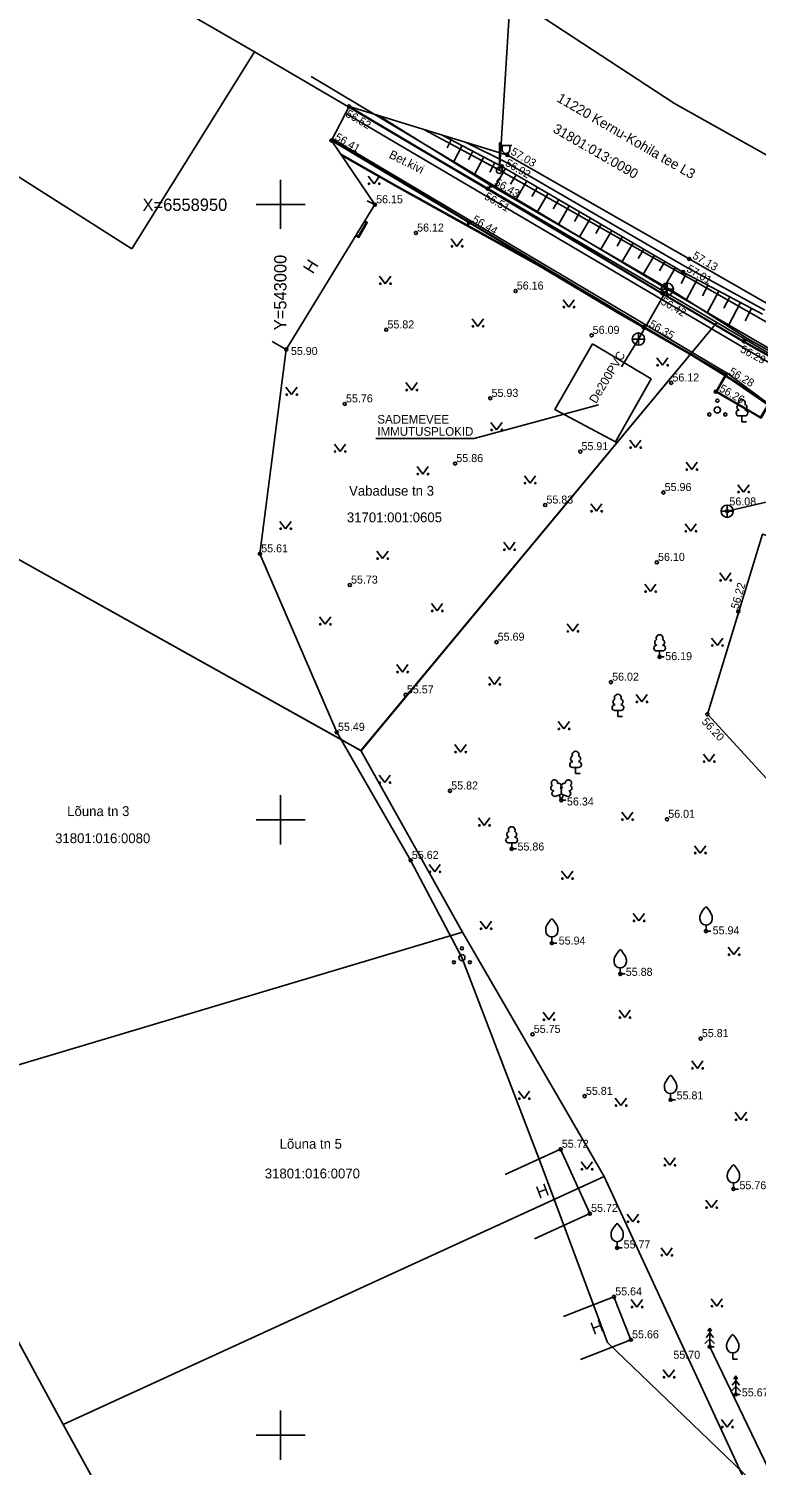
# Model space of a CAD drawing. Extents: x 542320 to 543602, y 6558748 to 6559969.
# Drawn here: x 542979.5 to 543038.7, y 6558847.6 to 6558964.3 of the extents above; entities that cross this region are included whole.
import ezdxf

# ---------------------------------------------------------------- set-up
doc = ezdxf.new("R2010")
doc.units = 0
for name, color, linetype in [('ABIJOONIS', 7, 'Continuous'), ('HALJASTUS', 7, 'Continuous'), ('HOONE', 7, 'Continuous'), ('HOONEDET', 7, 'Continuous'), ('KORGUS-EH2000', 7, 'Continuous'), ('mootpiir', 7, 'Continuous'), ('MPOHULIIN', 7, 'Continuous'), ('PIIR', 7, 'Continuous'), ('POST', 7, 'Continuous'), ('PUU', 7, 'Continuous'), ('RELJEEF', 7, 'Continuous'), ('SITRASS', 7, 'Continuous'), ('SKKAEV', 7, 'Continuous'), ('SKTRASS', 7, 'Continuous'), ('TEE', 7, 'Continuous'), ('VORK', 7, 'Continuous')]:
    doc.layers.add(name, color=color, linetype=linetype)

# ---------------------------------------------------------------- blocks, each defined once
blk = doc.blocks.new('VKORIS')
for p, q in [((0, 4), (0, -4)), ((-4, 0), (4, 0))]:
    blk.add_line(p, q)
blk = doc.blocks.new('VILJA1')
for p, q in [((0, 0), (0, 1)), ((0.8, 0), (0, 0))]:
    blk.add_line(p, q)
for points in [[(-1, 2), (-1, 2.3), (-0.98, 2.43), (-0.91, 2.69), (-0.79, 2.93), (-0.5, 3.4), (-0.18, 3.81), (0, 4)], [(1, 2), (1, 2.3), (0.98, 2.43), (0.91, 2.69), (0.79, 2.93), (0.5, 3.4), (0.18, 3.81), (0, 4)]]:
    blk.add_lwpolyline(points)
blk.add_arc((0, 2), 1, 180, 0)
blk = doc.blocks.new('KUUSK1')
for p, q in [((0, 3), (-0.3, 2.5)), ((0.3, 2.5), (0, 3)), ((0, 3), (0, 0)), ((0, 1.3), (-0.8, 0.5)), ((0, 2.2), (-0.6, 1.5)), ((0.6, 1.5), (0, 2.2)), ((0.8, 0.5), (0, 1.3)), ((0.72, 0), (0, 0))]:
    blk.add_line(p, q)
blk = doc.blocks.new('LEHTP1')
for p, q in [((0.48, 0.95), (-0.48, 0.95)), ((0, 0), (0, 0.95)), ((0.76, 0), (0, 0))]:
    blk.add_line(p, q)
for centre, radius, start, end in [((-0.34, 2.35), 0.465, 109.0217, 253.1415), ((0, 3.04), 0.554, 332.5799, 207.4201), ((0.34, 2.35), 0.465, 286.8508, 70.9859), ((-0.47, 1.42), 0.475, 90.0016, 269.3953), ((0.47, 1.42), 0.475, 270.6047, 89.9984)]:
    blk.add_arc(centre, radius, start, end)
blk = doc.blocks.new('MURU')
for p, q in [((-0.93, 1.21), (0, 0)), ((0, 0), (0.89, 1.21))]:
    blk.add_line(p, q)
for centre in [(-0.8, 0), (0.86, 0)]:
    blk.add_circle(centre, 0.11)
blk = doc.blocks.new('RING02')
blk.add_circle((0, 0), 0.25)
blk = doc.blocks.new('KAKAEV')
for p, q in [((-1, 0), (1, 0)), ((0, -1), (0, 1))]:
    blk.add_line(p, q)
blk.add_circle((0, 0), 1)
blk = doc.blocks.new('LEHTP2')
for p, q in [((-0.88, 0.67), (0.01, 1.02)), ((0, 0), (-0.35, 0.88)), ((0, 0), (0.36, 0.88)), ((0.76, 0), (0, 0)), ((0.01, 1.02), (0.89, 0.66))]:
    blk.add_line(p, q)
blk.add_lwpolyline([(0.01, 2.01), (-0.03, 1.86), (-0.03, 1.82), (-0.01, 1.76), (0.03, 1.69), (0.04, 1.65), (0.01, 1.58), (-0.04, 1.48), (-0.05, 1.43), (-0.04, 1.4), (-0.02, 1.34), (0.05, 1.22), (0.06, 1.18), (0.05, 1.14), (0.02, 1.07), (0.01, 1.02)])
for centre, radius, start, end in [((-1.26, 2.01), 0.448, 111.4304, 274.4987), ((-1.11, 2.83), 0.512, 111.5027, 232.5173), ((-1.11, 2.83), 0.512, 350.4856, 111.5002), ((-0.44, 2.33), 0.448, 308.5041, 111.5725), ((0.48, 2.32), 0.45, 67.7016, 230.5126), ((1.16, 2.81), 0.512, 67.6168, 188.6314), ((1.29, 1.99), 0.448, 264.6183, 67.6866), ((1.16, 2.81), 0.512, 306.5997, 67.6143), ((-1.05, 1.12), 0.475, 111.5014, 291.5004), ((0.01, 1.53), 0.475, 66.7655, 111.5015), ((1.07, 1.1), 0.475, 247.6166, 67.6155)]:
    blk.add_arc(centre, radius, start, end)
blk = doc.blocks.new('PQQSAS')
for centre, radius in [((0, 0), 0.5), ((0, 1.5), 0.25), ((-1.3, -0.75), 0.25), ((1.3, -0.75), 0.25)]:
    blk.add_circle(centre, radius)
blk = doc.blocks.new('PUPOST')
blk.add_circle((0, 0), 0.5)
blk = doc.blocks.new('VAPOST')
for p, q in [((0, 0.5), (0, 4.5)), ((0, 4), (2, 4)), ((0.45, 3.36), (0.45, 4)), ((1.68, 3.36), (1.68, 4))]:
    blk.add_line(p, q)
blk.add_arc((1.07, 3.36), 0.613, 180, 0)

msp = doc.modelspace()

# ---------------------------------------------------------------- linework, layer by layer
at = {"layer": 'ABIJOONIS'}
msp.add_lwpolyline([(543025.83, 6558933.7), (543015.73, 6558930.98), (543007.73, 6558930.98)], dxfattribs=at)
at = {"layer": 'HALJASTUS'}
msp.add_lwpolyline([(543034.87, 6558857.19), (543041.71, 6558842.99)], dxfattribs=at)
at = {"layer": 'HOONE'}
for points in [[(542999.32, 6558938.86), (543000.46, 6558938.21), (543007.66, 6558949.98), (543007.04, 6558950.3)], [(543018.24, 6558871.17), (543022.75, 6558873.23)], [(543022.75, 6558873.23), (543025.13, 6558868.02)], [(543020.63, 6558865.96), (543025.13, 6558868.02)], [(543022.99, 6558859.63), (543027.09, 6558861.24)], [(543028.46, 6558857.75), (543027.09, 6558861.24)], [(543024.36, 6558856.14), (543028.46, 6558857.75)]]:
    msp.add_lwpolyline(points, dxfattribs=at)
msp.add_lwpolyline([(543034.68, 6558908.57), (543039.15, 6558923.2), (543048.9, 6558920.3), (543046.15, 6558911.03), (543052.46, 6558904.09), (543051.99, 6558903.33), (543059.74, 6558898.9), (543060.25, 6558899.64), (543066.16, 6558898.37), (543069.06, 6558900.49), (543081.93, 6558897.71), (543079.79, 6558887.78), (543071.38, 6558889.62), (543068.48, 6558887.45), (543058.41, 6558889.58), (543048.6, 6558888.63), (543044.56, 6558897.82)], close=True, dxfattribs=at)
at = {"layer": 'HOONEDET'}
for points in [[(543006.11, 6558947.45), (543006.34, 6558947.31), (543007.04, 6558948.53), (543006.85, 6558948.65)], [(543006.15, 6558947.5), (543006.31, 6558947.4), (543006.96, 6558948.51), (543006.82, 6558948.59)]]:
    msp.add_lwpolyline(points, dxfattribs=at)
at = {"layer": 'mootpiir'}
msp.add_lwpolyline([(543041.71, 6558842.99), (543026.57, 6558857.52), (543021.18, 6558871.99), (543014.73, 6558888.8), (543010.56, 6558896.71), (543004.56, 6558907.11), (542998.32, 6558921.61), (543000.46, 6558938.21), (543007.66, 6558949.98), (543004.13, 6558955.19), (543005.56, 6558957.95), (543018.43, 6558954.01), (543033.2, 6558945.57), (543039.48, 6558941.98), (543051.3, 6558935.01), (543063.02, 6558928.65), (543075.18, 6558921.97), (543087.72, 6558915.09), (543097.04, 6558910.3), (543101.24, 6558907.88), (543109.9, 6558904.89), (543122.32, 6558898.43)], dxfattribs=at)
at = {"layer": 'MPOHULIIN'}
for points in [[(543017.78, 6558952.76), (543019.06, 6558973.25)], [(543099.4, 6558906.81), (543072.62, 6558921.95), (543045.5, 6558937.03), (543017.78, 6558952.77), (543011.7, 6558956.05)]]:
    msp.add_lwpolyline(points, dxfattribs=at)
at = {"layer": 'PIIR'}
for points in [[(543133.64, 6558888.72), (543040.58, 6558937.38), (543035.44, 6558940.39), (542997.88, 6558962.4), (542987.35, 6558968.48), (542985.46, 6558965.33), (542959.34, 6558980.79), (542961.33, 6558984.1), (542942.14, 6558992.15), (542929.74, 6558997.94), (542900.76, 6559010.27), (542901.6, 6559029.9)], [(542901.6, 6559029.9), (542917.01, 6559022.75), (542962.12, 6559001.91), (542973.99, 6558994.27), (542985.8, 6558986.59), (542988.44, 6558985.08), (543008.85, 6558971.63), (543009.57, 6558972.89), (543032.02, 6558958.19), (543053.45, 6558946.21), (543074.81, 6558934.76), (543108.64, 6558917.15), (543148.25, 6558900.44)], [(542974.22, 6558923.64), (542965.34, 6558941.81), (542975.88, 6558949.76), (542977.86, 6558952.77), (542987.9, 6558946.39), (542997.88, 6558962.4), (543035.44, 6558940.39), (543006.53, 6558905.61), (542974.22, 6558923.64)], [(543035.44, 6558940.39), (543040.58, 6558937.38), (543133.64, 6558888.72), (543159.27, 6558882.37), (543180.35, 6558877.33), (543188.6, 6558877.87), (543138.85, 6558855), (543136.39, 6558853.9), (543124.53, 6558851.31), (543111.21, 6558848.45), (543108.75, 6558866.73), (543082.72, 6558864.15), (543047.4, 6558848.41), (543054.87, 6558832.91), (543045.52, 6558829.45), (543026.29, 6558871.02), (543014.78, 6558890.86), (543006.52, 6558905.62), (543035.44, 6558940.39)], [(542950.84, 6558909.66), (542974.22, 6558923.64), (543006.52, 6558905.62), (543014.78, 6558890.86), (542968.16, 6558876.96), (542950.84, 6558909.66)], [(542968.16, 6558876.96), (543014.78, 6558890.86), (543026.29, 6558871.02), (542982.32, 6558850.86), (542968.16, 6558876.96)], [(542982.32, 6558850.86), (543026.29, 6558871.02), (543045.52, 6558829.45), (543010.9, 6558818.33), (543002.51, 6558814.16), (542982.32, 6558850.86)]]:
    msp.add_lwpolyline(points, dxfattribs=at)
at = {"layer": 'RELJEEF'}
for points in [[(543008.02, 6558957.17), (543017.09, 6558951.53), (543031.94, 6558942.92), (543037.97, 6558939.07)], [(543039.15, 6558941.08), (543032.71, 6558944.5), (543017.98, 6558953.09), (543013.17, 6558955.6)], [(543013.85, 6558955.25), (543013.52, 6558954.6)], [(543014.74, 6558954.78), (543014.04, 6558953.43)], [(543015.63, 6558954.32), (543015.26, 6558953.61)], [(543016.51, 6558953.86), (543015.74, 6558952.37)], [(543017.4, 6558953.39), (543016.99, 6558952.62)], [(543018.28, 6558952.92), (543017.37, 6558951.37)], [(543019.14, 6558952.41), (543018.69, 6558951.64)], [(543020, 6558951.91), (543019.11, 6558950.37)], [(543020.87, 6558951.41), (543020.42, 6558950.64)], [(543021.73, 6558950.9), (543020.84, 6558949.36)], [(543022.6, 6558950.4), (543022.15, 6558949.63)], [(543023.46, 6558949.89), (543022.57, 6558948.36)], [(543024.32, 6558949.39), (543023.88, 6558948.62)], [(543025.19, 6558948.89), (543024.3, 6558947.36)], [(543026.05, 6558948.38), (543025.61, 6558947.62)], [(543026.92, 6558947.88), (543026.03, 6558946.35)], [(543027.78, 6558947.38), (543027.34, 6558946.61)], [(543028.64, 6558946.87), (543027.76, 6558945.35)], [(543029.51, 6558946.37), (543029.06, 6558945.61)], [(543030.37, 6558945.86), (543029.49, 6558944.35)], [(543031.23, 6558945.36), (543030.79, 6558944.6)], [(543032.1, 6558944.86), (543031.22, 6558943.35)], [(543032.97, 6558944.36), (543032.55, 6558943.58)], [(543033.85, 6558943.89), (543032.98, 6558942.26)], [(543034.73, 6558943.42), (543034.28, 6558942.57)], [(543035.62, 6558942.95), (543034.67, 6558941.18)], [(543036.5, 6558942.49), (543036.01, 6558941.56)], [(543037.38, 6558942.02), (543036.36, 6558940.1)], [(543038.27, 6558941.55), (543037.74, 6558940.55)], [(543037.97, 6558939.07), (543049.99, 6558932.34), (543073.67, 6558919.4), (543086.31, 6558912.67), (543095.54, 6558907.79), (543101.9, 6558904.43)]]:
    msp.add_lwpolyline(points, dxfattribs=at)
at = {"layer": 'SITRASS'}
for points in [[(543005.22, 6558957.45), (543045, 6558934.01), (543059.2, 6558926.75), (543074.38, 6558918.33), (543088.21, 6558911.5)], [(543004.2, 6558955.33), (543036.37, 6558936.23), (543041.03, 6558932.77), (543041.48, 6558932.31)], [(543064.26, 6558899.01), (543071.81, 6558902.91), (543075.17, 6558904.48), (543076.76, 6558907.49), (543078.62, 6558910.61), (543079.63, 6558911.97), (543079.37, 6558912.8), (543070.45, 6558917.73), (543064, 6558920.82), (543057.14, 6558924.93), (543052.25, 6558927.86), (543046.19, 6558930.99), (543042.46, 6558932.62), (543041.21, 6558933.18), (543040.24, 6558933.33), (543036.74, 6558935.74), (543033.41, 6558937.8), (543027.38, 6558941.25), (543021.13, 6558945), (543014.59, 6558948.63), (543009.37, 6558951.53), (543004.89, 6558954.07)], [(543064.24, 6558899.05), (543071.79, 6558902.95), (543075.13, 6558904.52), (543076.72, 6558907.51), (543078.58, 6558910.64), (543079.57, 6558911.98), (543079.33, 6558912.77), (543070.43, 6558917.69), (543063.98, 6558920.78), (543057.11, 6558924.89), (543052.23, 6558927.82), (543046.17, 6558930.94), (543042.44, 6558932.57), (543041.2, 6558933.13), (543040.22, 6558933.28), (543036.71, 6558935.7), (543033.38, 6558937.76), (543027.35, 6558941.21), (543021.1, 6558944.96), (543014.57, 6558948.59), (543009.35, 6558951.49), (543004.96, 6558953.98)]]:
    msp.add_lwpolyline(points, dxfattribs=at)
at = {"layer": 'SKKAEV'}
msp.add_lwpolyline([(543025.34, 6558938.68), (543022.29, 6558933.33), (543027.22, 6558930.7), (543030.1, 6558935.82)], close=True, dxfattribs=at)
at = {"layer": 'SKTRASS'}
for points in [[(543002.49, 6558960.39), (543031.42, 6558943.1)], [(543029.08, 6558939.06), (543031.42, 6558943.1)], [(543031.42, 6558943.1), (543044.35, 6558935.57)], [(543027.69, 6558936.79), (543029.08, 6558939.06)], [(543036.29, 6558925.07), (543042.53, 6558926.5)]]:
    msp.add_lwpolyline(points, dxfattribs=at)
at = {"layer": 'TEE'}
for points in [[(543037.63, 6558938.82), (543031.01, 6558942.73), (543016.83, 6558951.22), (543005.53, 6558957.9)], [(543037.66, 6558938.87), (543031.03, 6558942.77), (543016.85, 6558951.27), (543005.56, 6558957.95)], [(543004.13, 6558955.19), (543015.3, 6558948.52), (543029.5, 6558940.02), (543036.16, 6558936.14)], [(543004.16, 6558955.24), (543015.32, 6558948.56), (543029.53, 6558940.06), (543036.19, 6558936.18)], [(543015.12, 6558954.99), (543018.2, 6558953.47), (543032.88, 6558944.94), (543039.34, 6558941.41)], [(543039.48, 6558941.98), (543033.2, 6558945.57), (543018.43, 6558954.01)], [(543037.63, 6558938.82), (543049.65, 6558932.04), (543061.27, 6558925.53), (543073.39, 6558919), (543086.03, 6558912.23), (543093.14, 6558908.47), (543101.87, 6558904.38), (543104.96, 6558903), (543105, 6558903.89), (543104.89, 6558904.29), (543104.48, 6558905.12), (543104.06, 6558905.54), (543103.37, 6558905.97), (543101.02, 6558907.1), (543101.35, 6558907.7)], [(543037.66, 6558938.87), (543049.68, 6558932.09), (543061.3, 6558925.58), (543073.42, 6558919.05), (543086.06, 6558912.28), (543093.17, 6558908.53), (543101.9, 6558904.43), (543104.9, 6558903.09), (543104.94, 6558903.89), (543104.84, 6558904.26), (543104.43, 6558905.08), (543104.02, 6558905.5), (543103.34, 6558905.91), (543100.94, 6558907.08), (543101.3, 6558907.73)], [(543043.42, 6558931.91), (543039.8, 6558933.97), (543039.04, 6558932.63), (543035.37, 6558934.78), (543036.16, 6558936.14)], [(543043.45, 6558931.97), (543039.78, 6558934.05), (543039.01, 6558932.71), (543035.46, 6558934.8), (543036.21, 6558936.11)]]:
    msp.add_lwpolyline(points, dxfattribs=at)

# ---------------------------------------------------------------- block references
at = {"layer": 'HALJASTUS', "xscale": 0.5, "yscale": 0.5}
for p in [(543007.59, 6558951.68), (543014.33, 6558946.59), (543008.5, 6558943.55), (543023.42, 6558941.65), (543016.03, 6558940.09), (543031.03, 6558936.93), (543010.65, 6558934.91), (543000.89, 6558934.54), (543017.55, 6558931.67), (543004.83, 6558929.92), (543028.84, 6558930.24), (543011.55, 6558928.09), (543033.41, 6558928.45), (543020.27, 6558927.35), (543037.62, 6558926.62), (543025.67, 6558925.07), (543000.4, 6558923.64), (543033.33, 6558923.44), (543018.59, 6558921.94), (543008.28, 6558921.22), (543036.15, 6558919.45), (543030.06, 6558918.54), (543003.62, 6558915.89), (543012.72, 6558916.97), (543023.74, 6558915.31), (543035.49, 6558914.16), (543009.9, 6558912), (543017.39, 6558911), (543029.35, 6558909.58), (543023.02, 6558907.38), (543014.62, 6558905.5), (543034.82, 6558904.73), (543008.46, 6558903.02), (543028.18, 6558900.01), (543016.55, 6558899.54), (543034.1, 6558897.29), (543012.53, 6558895.77), (543023.3, 6558895.22), (543029.12, 6558891.78), (543016.69, 6558891.15), (543036.84, 6558889.04), (543021.8, 6558883.75), (543027.97, 6558883.93), (543033.87, 6558879.8), (543019.79, 6558877.34), (543027.66, 6558876.78), (543037.41, 6558875.63), (543024.89, 6558871.61), (543031.63, 6558871.93), (543035.02, 6558868.49), (543028.63, 6558867.34), (543031.38, 6558864.61), (543028.96, 6558860.41), (543035.45, 6558860.48), (543031.56, 6558854.71), (543036.3, 6558850.66)]:
    msp.add_blockref('MURU', p, dxfattribs=at)
at = {"layer": 'KORGUS-EH2000', "xscale": 0.5, "yscale": 0.5}
for p in [(543005.56, 6558957.95), (543004.13, 6558955.19), (543018.43, 6558954.01), (543017.98, 6558953.09), (543017.09, 6558951.53), (543016.85, 6558951.27), (543007.66, 6558949.98), (543015.3, 6558948.52), (543010.99, 6558947.68), (543033.2, 6558945.57), (543032.71, 6558944.5), (543019.09, 6558942.96), (543031.03, 6558942.77), (543008.58, 6558939.81), (543029.5, 6558940.02), (543025.27, 6558939.36), (543037.66, 6558938.87), (543000.46, 6558938.21), (543031.74, 6558935.5), (543036.16, 6558936.14), (543017.04, 6558934.25), (543035.37, 6558934.78), (543005.21, 6558933.79), (543024.35, 6558929.91), (543014.18, 6558928.94), (543031.11, 6558926.59), (543021.5, 6558925.57), (543036.29, 6558925.07), (542998.32, 6558921.61), (543030.57, 6558920.91), (543005.62, 6558919.07), (543037.19, 6558916.92), (543017.54, 6558914.43), (543030.8, 6558913.24), (543026.84, 6558911.18), (543010.16, 6558910.15), (543034.68, 6558908.57), (543004.56, 6558907.11), (543013.76, 6558902.35), (543022.81, 6558901.58), (543031.4, 6558900.04), (543010.56, 6558896.71), (543018.78, 6558897.64), (543034.57, 6558890.95), (543022.04, 6558889.98), (543027.6, 6558887.47), (543020.47, 6558882.56), (543034.13, 6558882.22), (543024.71, 6558877.54), (543031.69, 6558877.25), (543022.75, 6558873.23), (543036.8, 6558870), (543025.13, 6558867.99), (543027.35, 6558865.22), (543027.09, 6558861.24), (543028.46, 6558857.75), (543034.87, 6558857.19), (543036.99, 6558853.31)]:
    msp.add_blockref('RING02', p, dxfattribs=at)
at = {"layer": 'POST', "xscale": 0.5, "yscale": 0.5}
for name in ['VAPOST', 'PUPOST']:
    msp.add_blockref(name, (543017.78, 6558952.77), dxfattribs=at)
at = {"layer": 'PUU', "xscale": 0.5, "yscale": 0.5}
for name, p in [('PQQSAS', (543035.49, 6558933.3)), ('LEHTP1', (543037.49, 6558932.34)), ('LEHTP1', (543030.8, 6558913.24)), ('LEHTP1', (543027.41, 6558908.4)), ('LEHTP1', (543023.97, 6558903.77)), ('LEHTP2', (543022.81, 6558901.58)), ('LEHTP1', (543018.78, 6558897.64)), ('VILJA1', (543034.57, 6558890.95)), ('VILJA1', (543022.04, 6558889.98)), ('PQQSAS', (543014.73, 6558888.8)), ('VILJA1', (543027.6, 6558887.47)), ('VILJA1', (543031.69, 6558877.25)), ('VILJA1', (543036.8, 6558870)), ('VILJA1', (543027.35, 6558865.22)), ('KUUSK1', (543034.87, 6558857.19)), ('VILJA1', (543036.74, 6558856.18)), ('KUUSK1', (543036.99, 6558853.31))]:
    msp.add_blockref(name, p, dxfattribs=at)
at = {"layer": 'SKKAEV', "xscale": 0.5, "yscale": 0.5}
for p in [(543031.42, 6558943.1), (543029.08, 6558939.06), (543036.29, 6558925.07)]:
    msp.add_blockref('KAKAEV', p, dxfattribs=at)
at = {"layer": 'VORK', "xscale": 0.5, "yscale": 0.5}
for p in [(543000, 6558950), (543000, 6558900), (543000, 6558850)]:
    msp.add_blockref('VKORIS', p, dxfattribs=at)

# ---------------------------------------------------------------- texts
at = {"layer": 'ABIJOONIS'}
for s, p in [('SADEMEVEE', (543007.86, 6558932.19)), ('IMMUTUSPLOKID ', (543007.86, 6558931.2))]:
    msp.add_text(s, height=0.7, dxfattribs=at).set_placement(p)
at = {"layer": 'HOONE'}
for rotation, p in [(57.8146, (543002.61, 6558944.29)), (20.8873, (543021, 6558869.2)), (20.8873, (543025.43, 6558858.14))]:
    msp.add_text('H', height=1, rotation=rotation, dxfattribs=at).set_placement(p)
at = {"layer": 'KORGUS-EH2000'}
for s, rotation, p in [('56.52', 329.7138, (543005.22, 6558957.18)), ('56.41', 329.7138, (543004.34, 6558955.28)), ('57.03', 329.7138, (543018.64, 6558954.1)), ('56.92', 329.7138, (543018.19, 6558953.18)), ('56.43', 329.7138, (543017.3, 6558951.62)), ('56.51', 329.7138, (543016.5, 6558950.47)), ('56.44', 329.7138, (543015.51, 6558948.6)), ('57.13', 329.7138, (543033.41, 6558945.66)), ('57.01', 329.7138, (543032.92, 6558944.59)), ('56.42', 329.7138, (543030.83, 6558941.94)), ('56.35', 329.7138, (543029.88, 6558940.1)), ('56.29', 331.4005, (543037.29, 6558938.04)), ('56.28', 329.7138, (543036.37, 6558936.23)), ('56.26', 330.0027, (543035.58, 6558934.86)), ('56.22', 74.2095, (543037.19, 6558917.07)), ('56.20', 312.5448, (543034.17, 6558907.93))]:
    msp.add_text(s, height=0.65, rotation=rotation, dxfattribs=at).set_placement(p)
for s, p in [('56.15', (543007.76, 6558950.09)), ('56.12', (543011.09, 6558947.79)), ('56.16', (543019.19, 6558943.08)), ('55.82', (543008.68, 6558939.92)), ('56.09', (543025.36, 6558939.48)), ('55.90', (543000.83, 6558937.76)), ('56.12', (543031.84, 6558935.61)), ('55.76', (543005.31, 6558933.91)), ('55.93', (543017.14, 6558934.36)), ('55.91', (543024.45, 6558930.03)), ('55.86', (543014.28, 6558929.06)), ('55.96', (543031.21, 6558926.71)), ('55.83', (543021.6, 6558925.69)), ('56.08', (543036.47, 6558925.54)), ('55.61', (542998.42, 6558921.73)), ('56.10', (543030.67, 6558921.03)), ('55.73', (543005.72, 6558919.19)), ('55.69', (543017.64, 6558914.55)), ('56.19', (543031.26, 6558912.97)), ('56.02', (543026.94, 6558911.3)), ('55.57', (543010.26, 6558910.27)), ('55.49', (543004.66, 6558907.23)), ('55.82', (543013.86, 6558902.46)), ('56.34', (543023.27, 6558901.16)), ('56.01', (543031.5, 6558900.16)), ('55.86', (543019.25, 6558897.5)), ('55.62', (543010.66, 6558896.82)), ('55.94', (543035.11, 6558890.69)), ('55.94', (543022.6, 6558889.86)), ('55.88', (543028.05, 6558887.32)), ('55.75', (543020.57, 6558882.68)), ('55.81', (543034.23, 6558882.34)), ('55.81', (543024.81, 6558877.65)), ('55.81', (543032.18, 6558877.28)), ('55.72', (543022.85, 6558873.35)), ('55.76', (543037.29, 6558869.98)), ('55.72', (543025.23, 6558868.14)), ('55.77', (543027.87, 6558865.17)), ('55.64', (543027.19, 6558861.36)), ('55.66', (543028.56, 6558857.87)), ('55.70', (543031.92, 6558856.21)), ('55.67', (543037.48, 6558853.15))]:
    msp.add_text(s, height=0.65, dxfattribs=at).set_placement(p)
at = {"layer": 'PIIR'}
for s, p in [('11220 Kernu-Kohila tee L3', (543022.38, 6558958.4)), ('31801:013:0090', (543022.06, 6558955.91))]:
    msp.add_text(s, height=0.8, rotation=329.9832, dxfattribs=at).set_placement(p)
for s, p in [('Vabaduse tn 3', (543005.56, 6558926.33)), ('31701:001:0605', (543005.38, 6558924.17)), ('Lõuna tn 3', (542982.65, 6558900.3)), ('31801:016:0080', (542981.67, 6558898.1)), ('Lõuna tn 5', (542999.92, 6558873.27)), ('31801:016:0070', (542998.71, 6558870.86))]:
    msp.add_text(s, height=0.8, dxfattribs=at).set_placement(p)
at = {"layer": 'SKKAEV'}
msp.add_text('De200PVC', height=0.7, rotation=59.0524, dxfattribs=at).set_placement((543025.63, 6558933.77))
at = {"layer": 'TEE'}
msp.add_text('Bet.kivi', height=0.7, rotation=333.1699, dxfattribs=at).set_placement((543008.74, 6558953.82))
at = {"layer": 'VORK'}
msp.add_text('X=6558950', height=1, dxfattribs=at).set_placement((542988.78, 6558949.47))
msp.add_text('Y=543000', height=1, rotation=90, dxfattribs=at).set_placement((543000.47, 6558939.77))

doc.saveas('drawing.dxf')
